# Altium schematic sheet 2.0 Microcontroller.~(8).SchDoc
size A4; SheetNumber: 2; SheetTotal: 6
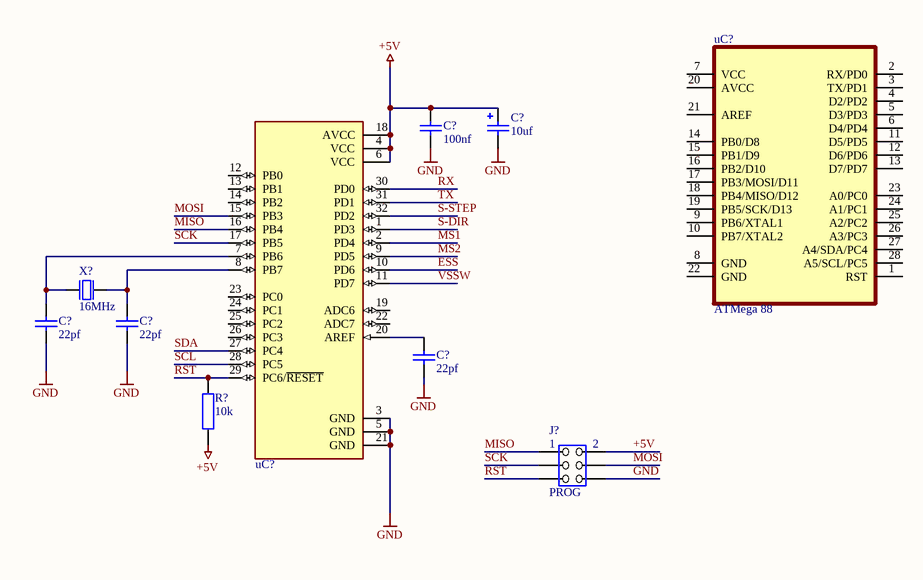
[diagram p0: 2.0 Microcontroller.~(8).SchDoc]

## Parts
(Parts that share a designator on the sheet are numbered #1, #2 ... from top to bottom, then left to right.)
C?#1  10uf  [C_SMD_D-TYP]
C?#2  100nf  [C_SMD_0805]
C?#3  22pf  [C_SMD_0805]
C?#4  22pf  [C_SMD_0805]
C?#5  22pf  [C_SMD_0805]
J?  PROG  [J_2x3]
R?  10k  [R_SMD_0805]
uC?#1  ATMega 88  [DIP-28]
uC?#2  ATMega328(p)-AU  [TQFP-32]  (value not drawn)
X?  16MHz  [X_SMD_XTAL]

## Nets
+5V: C?#1.1 C?#2.1 J?.2 R?.1 uC?#2.4(VCC) uC?#2.6(VCC) uC?#2.18(AVCC)
GND: C?#1.2 C?#2.2 C?#3.2 C?#4.2 C?#5.2 J?.6 uC?#2.3(GND) uC?#2.5(GND) uC?#2.21(GND)
ESS: uC?#2.10(PD6)
MISO: J?.1 uC?#2.16(PB4)
MOSI: J?.4 uC?#2.15(PB3)
MS1: uC?#2.2(PD4)
MS2: uC?#2.9(PD5)
RST: J?.5 R?.2 uC?#2.29(PC6/~{RESET})
RX: uC?#2.30(PD0)
S-DIR: uC?#2.1(PD3)
S-STEP: uC?#2.32(PD2)
SCK: J?.3 uC?#2.17(PB5)
SCL: uC?#2.28(PC5)
SDA: uC?#2.27(PC4)
TX: uC?#2.31(PD1)
VSSW: uC?#2.11(PD7)
NetC?#3_1: C?#3.1 uC?#2.7(PB6) X?.1
NetC?#4_1: C?#4.1 uC?#2.8(PB7) X?.2
NetC?#5_1: C?#5.1 uC?#2.20(AREF)

Not connected (* = marked no-connect by the designer): uC?#1 1(RST) 2(RX/PD0) 3(TX/PD1) 4(D2/PD2) 5(D3/PD3) 6(D4/PD4) 7(VCC) 8(GND) 9(PB6/XTAL1) 10(PB7/XTAL2) 11(D5/PD5) 12(D6/PD6) 13(D7/PD7) 14(PB0/D8) 15(PB1/D9) 16(PB2/D10) 17(PB3/MOSI/D11) 18(PB4/MISO/D12) 19(PB5/SCK/D13) 20(AVCC) 21(AREF) 22(GND) 23(A0/PC0) 24(A1/PC1) 25(A2/PC2) 26(A3/PC3) 27(A4/SDA/PC4) 28(A5/SCL/PC5); uC?#2 12(PB0) 13(PB1) 14(PB2) 19(ADC6) 22(ADC7) 23(PC0) 24(PC1) 25(PC2) 26(PC3)

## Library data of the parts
C?#1 = C_SMD_ELK: SMD Elektrolytkondensator
C?#2-C?#5 = C_SMD_KO: Kondensator SMD Universal, Keramik, Folie, usw.
J? = J_THT_IDC 2x3: Stecker
R? = R_SMD_Widerstand: Widerstand SMD
uC?#1 = UC_ATMega88-PU: Atmel ATMega88-PU; MP: ATMEGA88-20PU
uC?#2 = UC_ATMega328P-AU: Microcontroller
X? = X_SMD_Quarz: Quarz SMD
